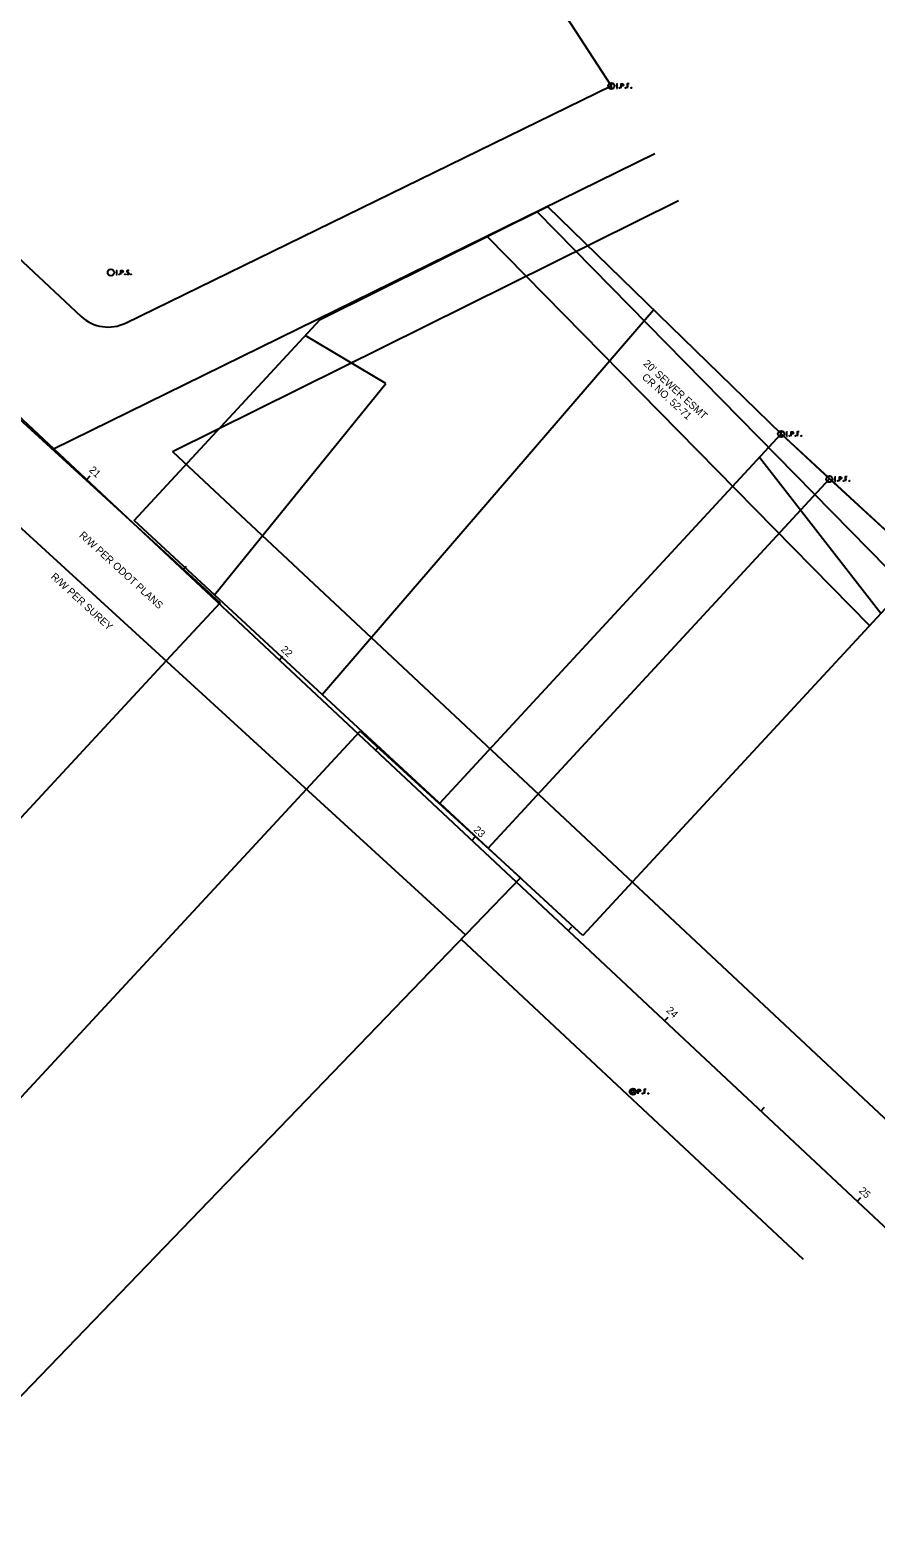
# Model space of a CAD drawing. Extents: x 1474076 to 1484331, y 375914 to 383395.
# Drawn here: x 1479633 to 1479954, y 379506 to 380077 of the extents above; entities that cross this region are included whole.
import ezdxf

# ---------------------------------------------------------------- set-up
doc = ezdxf.new("R2010")
doc.units = 0
for name, color, linetype in [('BD_X_Canopy', 7, 'Continuous'), ('DV_X_Property_Line', 7, 'Continuous'), ('RW_X_CL_20', 7, 'Continuous'), ('RW_X_Esmt_SH', 7, 'Continuous'), ('RW_X_Esmt_U', 7, 'Continuous'), ('SV_P_Mon_Cells_Set', 7, 'Continuous'), ('SV_X_Mon_Cells_Found', 7, 'Continuous'), ('SV_X_Text', 7, 'Continuous')]:
    doc.layers.add(name, color=color, linetype=linetype)

msp = doc.modelspace()

# ---------------------------------------------------------------- linework, layer by layer
at = {"layer": 'BD_X_Canopy'}
for p, q in [((1479744.07, 379825.66), (1479869.62, 379971.37)), ((1479768.21, 379943.5), (1479737.69, 379961.71)), ((1479703.24, 379863.4), (1479768.21, 379943.5)), ((1479788.64, 379784.45), (1479917.96, 379924.35)), ((1479705.39, 379860.37), (1479684.99, 379838.37)), ((1479684.99, 379838.37), (1479477.52, 379614.57)), ((1479738.11, 379789.75), (1479758.5, 379811.76)), ((1479528.47, 379563.5), (1479738.11, 379789.75))]:
    msp.add_line(p, q, dxfattribs=at)
at = {"layer": 'DV_X_Property_Line'}
for p, q in [((1479516.31, 380577.06), (1479853.6, 380056.19)), ((1479743.27, 379967.74), (1479829.42, 380010.48)), ((1479829.42, 380010.48), (1479917.96, 379924.35)), ((1479672.81, 379891.53), (1479743.27, 379967.74)), ((1479621.65, 379937.01), (1479705.39, 379860.37)), ((1479917.96, 379924.35), (1479936.32, 379907.39)), ((1479936.32, 379907.39), (1479917.96, 379924.35)), ((1479917.96, 379924.35), (1479972.23, 379874.23)), ((1479955.72, 379856.37), (1479909.79, 379915.51)), ((1479807, 379767.48), (1479936.32, 379907.39)), ((1479936.32, 379907.39), (1479972.23, 379874.23)), ((1479807, 379767.48), (1479672.81, 379891.53)), ((1479972.23, 379874.23), (1479842.89, 379734.31)), ((1479758.5, 379811.76), (1479819.17, 379756.22)), ((1479788.64, 379784.45), (1479807, 379767.48)), ((1479842.89, 379734.31), (1479807, 379767.48)), ((1479819.17, 379756.22), (1479798.35, 379734.62)), ((1479798.35, 379734.62), (1479581.86, 379510))]:
    msp.add_line(p, q, dxfattribs=at)
at = {"layer": 'RW_X_CL_20'}
for p, q in [((1479642.33, 379918.73), (1479870.13, 380030.67)), ((1479566.7, 379989.54), (1480555.97, 379063.33)), ((1479654.81, 379907.04), (1479656.18, 379908.5)), ((1479691.31, 379872.87), (1479692.68, 379874.33)), ((1479727.81, 379838.69), (1479729.18, 379840.15)), ((1479764.31, 379804.52), (1479765.68, 379805.98)), ((1479800.81, 379770.35), (1479802.18, 379771.81)), ((1479837.31, 379736.18), (1479838.68, 379737.64)), ((1479873.81, 379702), (1479875.18, 379703.46)), ((1479910.31, 379667.83), (1479911.68, 379669.29)), ((1479946.81, 379633.66), (1479948.18, 379635.12))]:
    msp.add_line(p, q, dxfattribs=at)
at = {"layer": 'RW_X_Esmt_SH'}
for p, q in [((1479669.64, 379966.37), (1479853.6, 380056.19)), ((1479687.35, 379917.68), (1479879.01, 380012.75)), ((1479607.65, 380011.05), (1479652.81, 379968.89)), ((1479687.35, 379917.68), (1479967.32, 379655.56))]:
    msp.add_line(p, q, dxfattribs=at)
msp.add_lwpolyline([(1479610.78, 379906.29), (1479798.35, 379734.62), (1479796.8, 379733.01), (1479926.31, 379611.76)], dxfattribs=at)
msp.add_arc((1479663.06, 379979.85), 15, 226.9362, 296.0142, dxfattribs=at)
at = {"layer": 'RW_X_Esmt_U'}
for p, q in [((1479825.48, 380008.52), (1479965.05, 379866.47)), ((1479806.63, 379999.17), (1479951.46, 379851.77))]:
    msp.add_line(p, q, dxfattribs=at)
at = {"layer": 'SV_P_Mon_Cells_Set'}
for points in [[(1479666.07, 379986.33), (1479666.42, 379986.33)], [(1479666.07, 379984.73), (1479666.42, 379984.73)], [(1479666.25, 379984.73), (1479666.25, 379986.33)], [(1479667.21, 379984.95), (1479667.26, 379984.95), (1479667.3, 379984.92), (1479667.33, 379984.87), (1479667.33, 379984.81), (1479667.3, 379984.76), (1479667.26, 379984.73), (1479667.21, 379984.73), (1479667.17, 379984.76), (1479667.14, 379984.81), (1479667.14, 379984.87), (1479667.17, 379984.92), (1479667.21, 379984.95)], [(1479667.81, 379984.73), (1479667.81, 379986.33), (1479668.34, 379986.33), (1479668.4, 379986.32), (1479668.47, 379986.29), (1479668.51, 379986.27), (1479668.54, 379986.24), (1479668.59, 379986.18), (1479668.62, 379986.12), (1479668.64, 379986.02), (1479668.64, 379985.86), (1479668.63, 379985.81), (1479668.61, 379985.74), (1479668.56, 379985.65), (1479668.52, 379985.61), (1479668.49, 379985.59), (1479668.43, 379985.56), (1479668.34, 379985.55), (1479667.81, 379985.55)], [(1479669.46, 379984.95), (1479669.51, 379984.95), (1479669.54, 379984.92), (1479669.58, 379984.87), (1479669.58, 379984.81), (1479669.54, 379984.76), (1479669.51, 379984.73), (1479669.46, 379984.73), (1479669.42, 379984.76), (1479669.39, 379984.81), (1479669.39, 379984.87), (1479669.42, 379984.92), (1479669.46, 379984.95)], [(1479670.82, 379986.22), (1479670.8, 379986.24), (1479670.77, 379986.27), (1479670.67, 379986.31), (1479670.55, 379986.33), (1479670.46, 379986.33), (1479670.43, 379986.33), (1479670.28, 379986.29), (1479670.16, 379986.22), (1479670.08, 379986.12), (1479670.06, 379986.02), (1479670.06, 379985.94), (1479670.08, 379985.84), (1479670.17, 379985.75), (1479670.78, 379985.37), (1479670.83, 379985.32), (1479670.86, 379985.27), (1479670.88, 379985.2), (1479670.88, 379985.12), (1479670.87, 379985.05), (1479670.86, 379985), (1479670.83, 379984.93), (1479670.81, 379984.88), (1479670.79, 379984.84), (1479670.76, 379984.81), (1479670.72, 379984.78), (1479670.68, 379984.76), (1479670.65, 379984.74), (1479670.55, 379984.73), (1479670.39, 379984.73), (1479670.29, 379984.76), (1479670.15, 379984.84), (1479670.06, 379984.92)], [(1479671.64, 379984.95), (1479671.69, 379984.95), (1479671.73, 379984.92), (1479671.76, 379984.87), (1479671.76, 379984.81), (1479671.73, 379984.76), (1479671.69, 379984.73), (1479671.64, 379984.73), (1479671.61, 379984.76), (1479671.57, 379984.81), (1479671.57, 379984.87), (1479671.61, 379984.92), (1479671.64, 379984.95)]]:
    msp.add_lwpolyline(points, dxfattribs=at)
msp.add_circle((1479664.05, 379985.53), 1.2, dxfattribs=at)
at = {"layer": 'SV_X_Mon_Cells_Found'}
for p, q in [((1479853.6, 380056.31), (1479853.6, 380055.42)), ((1479917.96, 379924.46), (1479917.96, 379923.58))]:
    msp.add_line(p, q, dxfattribs=at)
for points in [[(1479855.63, 380056.99), (1479855.98, 380056.99)], [(1479855.8, 380055.39), (1479855.8, 380056.99)], [(1479857.37, 380055.39), (1479857.37, 380056.99), (1479857.9, 380056.99), (1479857.95, 380056.98), (1479858.03, 380056.95), (1479858.06, 380056.93), (1479858.1, 380056.9), (1479858.14, 380056.84), (1479858.17, 380056.78), (1479858.2, 380056.68), (1479858.2, 380056.52), (1479858.19, 380056.47), (1479858.16, 380056.4), (1479858.12, 380056.31), (1479858.08, 380056.27), (1479858.04, 380056.25), (1479857.99, 380056.22), (1479857.9, 380056.21), (1479857.37, 380056.21)], [(1479860.38, 380056.99), (1479859.62, 380056.99), (1479859.62, 380055.39)], [(1479855.63, 380055.39), (1479855.98, 380055.39)], [(1479856.76, 380055.6), (1479856.82, 380055.6), (1479856.85, 380055.58), (1479856.88, 380055.53), (1479856.88, 380055.47), (1479856.85, 380055.42), (1479856.82, 380055.39), (1479856.76, 380055.39), (1479856.73, 380055.42), (1479856.7, 380055.47), (1479856.7, 380055.53), (1479856.73, 380055.58), (1479856.76, 380055.6)], [(1479859.01, 380055.6), (1479859.07, 380055.6), (1479859.1, 380055.58), (1479859.13, 380055.53), (1479859.13, 380055.47), (1479859.1, 380055.42), (1479859.07, 380055.39), (1479859.01, 380055.39), (1479858.98, 380055.42), (1479858.95, 380055.47), (1479858.95, 380055.53), (1479858.98, 380055.58), (1479859.01, 380055.6)], [(1479859.62, 380056.21), (1479860.16, 380056.21)], [(1479861.16, 380055.6), (1479861.22, 380055.6), (1479861.25, 380055.58), (1479861.28, 380055.53), (1479861.28, 380055.47), (1479861.25, 380055.42), (1479861.22, 380055.39), (1479861.16, 380055.39), (1479861.13, 380055.42), (1479861.1, 380055.47), (1479861.1, 380055.53), (1479861.13, 380055.58), (1479861.16, 380055.6)], [(1479919.99, 379925.15), (1479920.34, 379925.15)], [(1479919.99, 379923.55), (1479920.34, 379923.55)], [(1479920.16, 379923.55), (1479920.16, 379925.15)], [(1479921.12, 379923.76), (1479921.18, 379923.76), (1479921.21, 379923.74), (1479921.24, 379923.69), (1479921.24, 379923.62), (1479921.21, 379923.57), (1479921.18, 379923.55), (1479921.12, 379923.55), (1479921.09, 379923.57), (1479921.06, 379923.62), (1479921.06, 379923.69), (1479921.09, 379923.74), (1479921.12, 379923.76)], [(1479921.73, 379923.55), (1479921.73, 379925.15), (1479922.26, 379925.15), (1479922.31, 379925.13), (1479922.39, 379925.11), (1479922.42, 379925.08), (1479922.46, 379925.06), (1479922.5, 379925), (1479922.53, 379924.93), (1479922.56, 379924.83), (1479922.56, 379924.68), (1479922.54, 379924.63), (1479922.52, 379924.55), (1479922.48, 379924.47), (1479922.43, 379924.43), (1479922.4, 379924.4), (1479922.35, 379924.38), (1479922.26, 379924.37), (1479921.73, 379924.37)], [(1479923.37, 379923.76), (1479923.43, 379923.76), (1479923.46, 379923.74), (1479923.49, 379923.69), (1479923.49, 379923.62), (1479923.46, 379923.57), (1479923.43, 379923.55), (1479923.37, 379923.55), (1479923.34, 379923.57), (1479923.31, 379923.62), (1479923.31, 379923.69), (1479923.34, 379923.74), (1479923.37, 379923.76)], [(1479924.74, 379925.15), (1479923.98, 379925.15), (1479923.98, 379923.55)], [(1479923.98, 379924.37), (1479924.52, 379924.37)], [(1479925.52, 379923.76), (1479925.58, 379923.76), (1479925.61, 379923.74), (1479925.64, 379923.69), (1479925.64, 379923.62), (1479925.61, 379923.57), (1479925.58, 379923.55), (1479925.52, 379923.55), (1479925.49, 379923.57), (1479925.45, 379923.62), (1479925.45, 379923.69), (1479925.49, 379923.74), (1479925.52, 379923.76)], [(1479938.25, 379908.07), (1479938.61, 379908.07)], [(1479938.25, 379906.47), (1479938.61, 379906.47)], [(1479938.43, 379906.47), (1479938.43, 379908.07)], [(1479939.39, 379906.69), (1479939.44, 379906.69), (1479939.48, 379906.66), (1479939.51, 379906.61), (1479939.51, 379906.55), (1479939.48, 379906.5), (1479939.44, 379906.47), (1479939.39, 379906.47), (1479939.36, 379906.5), (1479939.32, 379906.55), (1479939.32, 379906.61), (1479939.36, 379906.66), (1479939.39, 379906.69)], [(1479940, 379906.47), (1479940, 379908.07), (1479940.52, 379908.07), (1479940.58, 379908.06), (1479940.66, 379908.03), (1479940.69, 379908.01), (1479940.72, 379907.98), (1479940.77, 379907.92), (1479940.8, 379907.86), (1479940.82, 379907.76), (1479940.82, 379907.61), (1479940.81, 379907.55), (1479940.79, 379907.48), (1479940.74, 379907.39), (1479940.7, 379907.35), (1479940.67, 379907.33), (1479940.61, 379907.3), (1479940.52, 379907.29), (1479940, 379907.29)], [(1479941.64, 379906.69), (1479941.69, 379906.69), (1479941.73, 379906.66), (1479941.76, 379906.61), (1479941.76, 379906.55), (1479941.73, 379906.5), (1479941.69, 379906.47), (1479941.64, 379906.47), (1479941.6, 379906.5), (1479941.57, 379906.55), (1479941.57, 379906.61), (1479941.6, 379906.66), (1479941.64, 379906.69)], [(1479943, 379908.07), (1479942.24, 379908.07), (1479942.24, 379906.47)], [(1479942.24, 379907.29), (1479942.78, 379907.29)], [(1479943.79, 379906.69), (1479943.84, 379906.69), (1479943.88, 379906.66), (1479943.91, 379906.61), (1479943.91, 379906.55), (1479943.88, 379906.5), (1479943.84, 379906.47), (1479943.79, 379906.47), (1479943.75, 379906.5), (1479943.72, 379906.55), (1479943.72, 379906.61), (1479943.75, 379906.66), (1479943.79, 379906.69)], [(1479863.8, 379674.43), (1479863.8, 379676.03), (1479864.33, 379676.03), (1479864.38, 379676.01), (1479864.46, 379675.99), (1479864.49, 379675.96), (1479864.52, 379675.94), (1479864.57, 379675.88), (1479864.6, 379675.81), (1479864.62, 379675.71), (1479864.62, 379675.56), (1479864.61, 379675.51), (1479864.59, 379675.43), (1479864.55, 379675.35), (1479864.5, 379675.31), (1479864.47, 379675.28), (1479864.41, 379675.26), (1479864.33, 379675.25), (1479863.8, 379675.25)], [(1479865.44, 379674.64), (1479865.49, 379674.64), (1479865.53, 379674.62), (1479865.56, 379674.57), (1479865.56, 379674.5), (1479865.53, 379674.45), (1479865.49, 379674.43), (1479865.44, 379674.43), (1479865.41, 379674.45), (1479865.37, 379674.5), (1479865.37, 379674.57), (1479865.41, 379674.62), (1479865.44, 379674.64)], [(1479866.81, 379676.03), (1479866.04, 379676.03), (1479866.04, 379674.43)], [(1479866.04, 379675.25), (1479866.59, 379675.25)], [(1479867.59, 379674.64), (1479867.64, 379674.64), (1479867.68, 379674.62), (1479867.71, 379674.57), (1479867.71, 379674.5), (1479867.68, 379674.45), (1479867.64, 379674.43), (1479867.59, 379674.43), (1479867.55, 379674.45), (1479867.52, 379674.5), (1479867.52, 379674.57), (1479867.55, 379674.62), (1479867.59, 379674.64)]]:
    msp.add_lwpolyline(points, dxfattribs=at)
for centre, radius in [((1479853.6, 380056.19), 1.2), ((1479853.6, 380056.84), 0.16), ((1479917.96, 379924.35), 1.2), ((1479917.96, 379925), 0.16), ((1479936.24, 379907.27), 1.2), ((1479861.8, 379675.23), 1.2), ((1479861.8, 379675.23), 0.495)]:
    msp.add_circle(centre, radius, dxfattribs=at)

# ---------------------------------------------------------------- texts
at = {"layer": 'RW_X_CL_20'}
for s, p in [('21', (1479655.57, 379910.44)), ('22', (1479728.23, 379842.41)), ('23', (1479801.21, 379774.09)), ('24', (1479874.24, 379705.71)), ('25', (1479947.21, 379637.39))]:
    msp.add_text(s, height=2.8, rotation=316.8859, dxfattribs=at).set_placement(p)
at = {"layer": 'SV_X_Text'}
for s, p in [("20' SEWER ESMT", (1479865.51, 379950.7)), ('CR NO. 52-71', (1479864.98, 379945.54)), ('R/W PER ODOT PLANS', (1479651.85, 379885.66)), ('R/W PER SUREY', (1479641.08, 379869.97))]:
    msp.add_text(s, height=2.8, rotation=317.5331, dxfattribs=at).set_placement(p)

doc.saveas('drawing.dxf')
